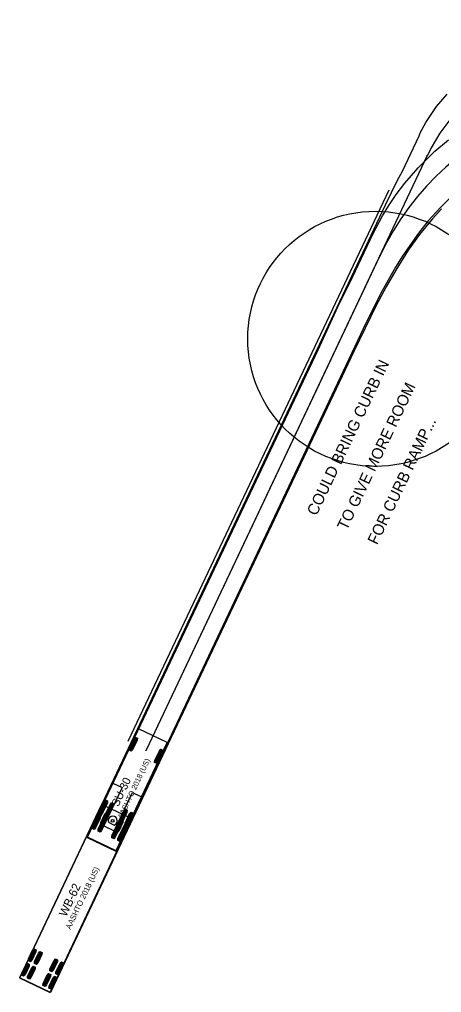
# Model space of a CAD drawing. Extents: x 186128 to 186702, y 352195 to 353183.
# Drawn here: x 186128.4 to 186233.9, y 352195.3 to 352438.5 of the extents above; entities that cross this region are included whole.
import ezdxf

# ---------------------------------------------------------------- set-up
doc = ezdxf.new("R2010")
doc.units = 0
for name, color, linetype in [('GK_Drainage_Nodes', 7, 'Continuous'), ('SV_X_Control_Cells_Found', 7, 'Continuous'), ('SV_X_Shot_Marker', 7, 'Continuous')]:
    doc.layers.add(name, color=color, linetype=linetype)

msp = doc.modelspace()

# ---------------------------------------------------------------- linework, layer by layer
at = {"layer": 'GK_Drainage_Nodes'}
msp.add_circle((186217.39, 352358.7), 31.89, dxfattribs=at)
at = {"layer": 'SV_X_Control_Cells_Found'}
for p, q in [((186218.52, 352379.47), (186160.05, 352255.86)), ((186158.14, 352261.18), (186145.31, 352234.06)), ((186165.37, 352257.76), (186158.14, 352261.18)), ((186158.14, 352261.18), (186158.14, 352261.18)), ((186157.33, 352258.99), (186155.91, 352255.97)), ((186157.52, 352258.9), (186156.09, 352255.88)), ((186157.71, 352258.81), (186156.28, 352255.79)), ((186152.54, 352230.64), (186165.37, 352257.76)), ((186163.81, 352255.92), (186162.38, 352252.91)), ((186164, 352255.83), (186162.57, 352252.82)), ((186164.19, 352255.74), (186162.76, 352252.73)), ((186148.78, 352240.91), (186147.35, 352237.89)), ((186148.97, 352240.82), (186147.54, 352237.8)), ((186149.16, 352240.73), (186147.73, 352237.71)), ((186150.13, 352240.26), (186148.71, 352237.25)), ((186150.32, 352240.18), (186148.9, 352237.16)), ((186150.51, 352240.09), (186149.09, 352237.07)), ((186153.9, 352238.48), (186152.48, 352235.47)), ((186154.09, 352238.39), (186152.66, 352235.38)), ((186154.28, 352238.3), (186152.85, 352235.29)), ((186155.26, 352237.84), (186153.83, 352234.83)), ((186155.45, 352237.75), (186154.02, 352234.74)), ((186155.63, 352237.66), (186154.21, 352234.65)), ((186145.31, 352234.06), (186152.54, 352230.64))]:
    msp.add_line(p, q, dxfattribs=at)
for points in [[(186222.28, 352394.26), (186222.38, 352394.42), (186224.74, 352397.64), (186228.09, 352401.48), (186232.25, 352405.58), (186235.67, 352408.47)], [(186237.37, 352395.21), (186233.67, 352391.54), (186230.61, 352388.16), (186228.19, 352385.14), (186224.25, 352379.56), (186222.44, 352376.64), (186219.1, 352370.74), (186215.13, 352362.76), (186153.42, 352232.25), (186152.66, 352230.71), (186152.56, 352230.68), (186145.38, 352234.09), (186203.09, 352355.91), (186208.04, 352366.67), (186210.96, 352372.57), (186216.83, 352385.07), (186219.16, 352389.47), (186220.77, 352392.06), (186222.28, 352394.26)], [(186157.28, 352259.01), (186157.75, 352258.78), (186157.7, 352258.3), (186156.67, 352256.13), (186156.33, 352255.77), (186155.86, 352255.99), (186155.92, 352256.48), (186156.94, 352258.65), (186157.28, 352259.01)], [(186163.76, 352255.94), (186164.23, 352255.72), (186164.18, 352255.23), (186163.15, 352253.06), (186162.81, 352252.71), (186162.34, 352252.93), (186162.4, 352253.42), (186163.42, 352255.59), (186163.76, 352255.94)], [(186148.73, 352240.93), (186149.2, 352240.71), (186149.14, 352240.22), (186148.12, 352238.05), (186147.78, 352237.69), (186147.31, 352237.92), (186147.36, 352238.4), (186148.39, 352240.57), (186148.73, 352240.93)], [(186150.09, 352240.29), (186150.56, 352240.06), (186150.5, 352239.58), (186149.47, 352237.41), (186149.13, 352237.05), (186148.66, 352237.27), (186148.72, 352237.76), (186149.75, 352239.93), (186150.09, 352240.29)], [(186153.85, 352238.51), (186154.32, 352238.28), (186154.27, 352237.79), (186153.24, 352235.62), (186152.9, 352235.27), (186152.43, 352235.49), (186152.49, 352235.98), (186153.51, 352238.15), (186153.85, 352238.51)], [(186155.21, 352237.86), (186155.68, 352237.64), (186155.62, 352237.15), (186154.6, 352234.98), (186154.26, 352234.63), (186153.79, 352234.85), (186153.84, 352235.34), (186154.87, 352237.51), (186155.21, 352237.86)]]:
    msp.add_lwpolyline(points, dxfattribs=at)
for centre in [(186218.52, 352379.47), (186218.52, 352379.47), (186160.05, 352255.86)]:
    msp.add_circle(centre, 0.0417, dxfattribs=at)
msp.add_arc((186281.8, 352349.54), 70, 65.2343, 154.6831, dxfattribs=at)
at = {"layer": 'SV_X_Shot_Marker'}
for p, q in [((186230.38, 352404.54), (186160.05, 352255.86)), ((186220.75, 352395.88), (186155.53, 352258)), ((186158.14, 352261.18), (186151.73, 352247.62)), ((186165.37, 352257.76), (186158.14, 352261.18)), ((186158.14, 352261.18), (186158.14, 352261.18)), ((186157.42, 352259.13), (186155.85, 352255.81)), ((186157.63, 352259.03), (186156.06, 352255.71)), ((186157.84, 352258.93), (186156.27, 352255.62)), ((186158.96, 352244.2), (186165.37, 352257.76)), ((186163.82, 352256.1), (186162.26, 352252.78)), ((186164.03, 352256), (186162.46, 352252.69)), ((186164.24, 352255.9), (186162.67, 352252.59)), ((186154.05, 352246.53), (186149.51, 352236.94)), ((186151.73, 352247.62), (186154.05, 352246.53)), ((186152.11, 352235.72), (186156.64, 352245.3)), ((186156.64, 352245.3), (186158.96, 352244.2)), ((186148.93, 352242.31), (186128.41, 352198.92)), ((186149.98, 352243.4), (186148.41, 352240.08)), ((186150.19, 352243.3), (186148.62, 352239.99)), ((186150.4, 352243.2), (186148.83, 352239.89)), ((186156.62, 352238.67), (186148.93, 352242.31)), ((186148.93, 352242.31), (186148.93, 352242.31)), ((186151.47, 352242.69), (186149.9, 352239.38)), ((186151.68, 352242.59), (186150.11, 352239.28)), ((186151.89, 352242.5), (186150.32, 352239.18)), ((186136.09, 352195.28), (186156.62, 352238.67)), ((186148.18, 352239.6), (186146.62, 352236.29)), ((186148.39, 352239.5), (186146.82, 352236.19)), ((186148.6, 352239.41), (186147.03, 352236.09)), ((186149.68, 352238.9), (186148.11, 352235.58)), ((186149.88, 352238.8), (186148.32, 352235.48)), ((186150.09, 352238.7), (186148.52, 352235.39)), ((186154.89, 352241.07), (186153.32, 352237.76)), ((186155.1, 352240.98), (186153.53, 352237.66)), ((186155.31, 352240.88), (186153.74, 352237.56)), ((186156.38, 352240.37), (186154.82, 352237.05)), ((186156.59, 352240.27), (186155.02, 352236.96)), ((186156.8, 352240.17), (186155.23, 352236.86)), ((186149.51, 352236.94), (186152.11, 352235.72)), ((186150.63, 352237.85), (186152.09, 352237.15)), ((186153.1, 352237.28), (186151.53, 352233.96)), ((186153.3, 352237.18), (186151.74, 352233.87)), ((186153.51, 352237.08), (186151.94, 352233.77)), ((186154.59, 352236.57), (186153.02, 352233.26)), ((186154.79, 352236.47), (186153.23, 352233.16)), ((186155, 352236.38), (186153.43, 352233.06)), ((186132.1, 352206.19), (186130.69, 352203.2)), ((186132.31, 352206.09), (186130.9, 352203.11)), ((186132.52, 352205.99), (186131.1, 352203.01)), ((186133.59, 352205.48), (186132.18, 352202.5)), ((186133.8, 352205.38), (186132.39, 352202.4)), ((186134.01, 352205.29), (186132.6, 352202.3)), ((186130.39, 352202.57), (186128.98, 352199.59)), ((186130.6, 352202.47), (186129.19, 352199.49)), ((186130.8, 352202.37), (186129.39, 352199.39)), ((186137.46, 352203.65), (186136.05, 352200.67)), ((186137.67, 352203.55), (186136.26, 352200.57)), ((186137.88, 352203.45), (186136.47, 352200.47)), ((186138.96, 352202.94), (186137.54, 352199.96)), ((186139.16, 352202.85), (186137.75, 352199.86)), ((186139.37, 352202.75), (186137.96, 352199.76)), ((186131.88, 352201.87), (186130.47, 352198.88)), ((186132.09, 352201.77), (186130.68, 352198.78)), ((186132.3, 352201.67), (186130.89, 352198.69)), ((186135.75, 352200.03), (186134.34, 352197.05)), ((186135.96, 352199.94), (186134.55, 352196.95)), ((186136.17, 352199.84), (186134.76, 352196.85)), ((186128.41, 352198.92), (186136.09, 352195.28)), ((186137.25, 352199.33), (186135.83, 352196.35)), ((186137.45, 352199.23), (186136.04, 352196.25)), ((186137.66, 352199.13), (186136.25, 352196.15))]:
    msp.add_line(p, q, dxfattribs=at)
for points in [[(186204.16, 352358.9), (186204.23, 352359.06), (186219.91, 352392.23), (186222.96, 352398.4), (186224.21, 352400.63), (186228.38, 352409.46), (186228.7, 352410.34), (186230.02, 352412.8), (186231.3, 352414.8), (186232.71, 352416.74), (186235.36, 352419.86)], [(186233.95, 352391.21), (186231.56, 352388.62), (186228.41, 352384.75), (186225.62, 352380.85), (186222.47, 352375.86), (186220.11, 352371.73), (186217.68, 352367.2), (186211.97, 352355.55), (186136.18, 352195.32), (186128.47, 352198.92), (186204.16, 352358.9)], [(186157.37, 352259.15), (186157.89, 352258.91), (186157.82, 352258.37), (186156.69, 352255.98), (186156.32, 352255.59), (186155.8, 352255.84), (186155.87, 352256.37), (186156.99, 352258.76), (186157.37, 352259.15)], [(186163.77, 352256.12), (186164.29, 352255.88), (186164.23, 352255.34), (186163.1, 352252.95), (186162.72, 352252.56), (186162.21, 352252.81), (186162.27, 352253.35), (186163.4, 352255.73), (186163.77, 352256.12)], [(186149.93, 352243.42), (186150.45, 352243.18), (186150.38, 352242.64), (186149.25, 352240.25), (186148.88, 352239.86), (186148.36, 352240.11), (186148.43, 352240.65), (186149.55, 352243.03), (186149.93, 352243.42)], [(186151.42, 352242.72), (186151.94, 352242.47), (186151.87, 352241.93), (186150.75, 352239.55), (186150.37, 352239.16), (186149.85, 352239.4), (186149.92, 352239.94), (186151.05, 352242.33), (186151.42, 352242.72)], [(186154.84, 352241.1), (186155.36, 352240.85), (186155.29, 352240.32), (186154.17, 352237.93), (186153.79, 352237.54), (186153.27, 352237.78), (186153.34, 352238.32), (186154.47, 352240.71), (186154.84, 352241.1)], [(186148.13, 352239.63), (186148.65, 352239.38), (186148.59, 352238.84), (186147.46, 352236.46), (186147.08, 352236.07), (186146.57, 352236.31), (186146.63, 352236.85), (186147.76, 352239.24), (186148.13, 352239.63)], [(186149.62, 352238.92), (186150.14, 352238.68), (186150.08, 352238.14), (186148.95, 352235.75), (186148.57, 352235.36), (186148.06, 352235.61), (186148.12, 352236.14), (186149.25, 352238.53), (186149.62, 352238.92)], [(186156.33, 352240.39), (186156.85, 352240.15), (186156.79, 352239.61), (186155.66, 352237.22), (186155.28, 352236.83), (186154.76, 352237.08), (186154.83, 352237.62), (186155.96, 352240), (186156.33, 352240.39)], [(186153.04, 352237.3), (186153.56, 352237.06), (186153.5, 352236.52), (186152.37, 352234.13), (186151.99, 352233.74), (186151.48, 352233.99), (186151.54, 352234.53), (186152.67, 352236.91), (186153.04, 352237.3)], [(186154.54, 352236.6), (186155.05, 352236.35), (186154.99, 352235.81), (186153.86, 352233.43), (186153.49, 352233.04), (186152.97, 352233.28), (186153.03, 352233.82), (186154.16, 352236.21), (186154.54, 352236.6)], [(186132.05, 352206.21), (186132.57, 352205.97), (186132.52, 352205.48), (186131.51, 352203.33), (186131.16, 352202.98), (186130.64, 352203.23), (186130.68, 352203.72), (186131.7, 352205.87), (186132.05, 352206.21)], [(186133.54, 352205.51), (186134.06, 352205.26), (186134.02, 352204.77), (186133, 352202.62), (186132.65, 352202.28), (186132.13, 352202.52), (186132.17, 352203.01), (186133.19, 352205.16), (186133.54, 352205.51)], [(186130.34, 352202.6), (186130.86, 352202.35), (186130.81, 352201.86), (186129.8, 352199.71), (186129.45, 352199.37), (186128.93, 352199.61), (186128.97, 352200.1), (186129.99, 352202.25), (186130.34, 352202.6)], [(186137.41, 352203.67), (186137.93, 352203.43), (186137.89, 352202.94), (186136.87, 352200.79), (186136.52, 352200.45), (186136, 352200.69), (186136.04, 352201.18), (186137.06, 352203.33), (186137.41, 352203.67)], [(186138.9, 352202.97), (186139.42, 352202.72), (186139.38, 352202.23), (186138.36, 352200.08), (186138.01, 352199.74), (186137.49, 352199.99), (186137.54, 352200.48), (186138.55, 352202.62), (186138.9, 352202.97)], [(186131.83, 352201.89), (186132.35, 352201.65), (186132.31, 352201.15), (186131.29, 352199.01), (186130.94, 352198.66), (186130.42, 352198.91), (186130.46, 352199.4), (186131.48, 352201.55), (186131.83, 352201.89)], [(186135.7, 352200.06), (186136.22, 352199.81), (186136.18, 352199.32), (186135.16, 352197.17), (186134.81, 352196.83), (186134.29, 352197.07), (186134.33, 352197.57), (186135.35, 352199.71), (186135.7, 352200.06)], [(186137.19, 352199.35), (186137.71, 352199.11), (186137.67, 352198.62), (186136.65, 352196.47), (186136.3, 352196.12), (186135.78, 352196.37), (186135.82, 352196.86), (186136.84, 352199.01), (186137.19, 352199.35)]]:
    msp.add_lwpolyline(points, dxfattribs=at)
for centre, radius in [((186230.38, 352404.54), 0.0417), ((186230.38, 352404.54), 0.0417), ((186160.05, 352255.86), 0.0417), ((186151.71, 352238.23), 0.34)]:
    msp.add_circle(centre, radius, dxfattribs=at)
for centre, radius, start, end in [((186282.23, 352476.39), 55, 154.4396, 252.2963), ((186268.35, 352386.58), 42, 65.2343, 154.6831), ((186151.71, 352238.23), 1.14, 289.6831, 199.6831)]:
    msp.add_arc(centre, radius, start, end, dxfattribs=at)

# ---------------------------------------------------------------- texts
at = {"layer": 'GK_Drainage_Nodes'}
for s, p in [('COULD BRING CURB IN ', (186202.66, 352314.28)), ('TO GIVE MORE ROOM ', (186210.24, 352310.66)), ('FOR CURB RAMP...', (186217.82, 352307.05))]:
    msp.add_text(s, height=2.8, rotation=64.5098, dxfattribs=at).set_placement(p)
at = {"layer": 'SV_X_Control_Cells_Found'}
for s, height, p in [('AASHTO 2018 (US)', 1.3333, (186154.07, 352238.53)), ('SU-30', 2, (186153.12, 352241.59)), ('(c) 2025 Transoft Solutions, Inc. All rights reserved.', 0.08, (186154.68, 352244.42))]:
    msp.add_text(s, height=height, rotation=64.6831, dxfattribs=at).set_placement(p)
at = {"layer": 'SV_X_Shot_Marker'}
for s, height, p in [('AASHTO 2018 (US)', 1.4167, (186141.16, 352210.95)), ('WB-62', 2.125, (186140.09, 352214.07)), ('(c) 2025 Transoft Solutions, Inc. All rights reserved.', 0.085, (186141.81, 352217.2))]:
    msp.add_text(s, height=height, rotation=64.6831, dxfattribs=at).set_placement(p)

doc.saveas('drawing.dxf')
